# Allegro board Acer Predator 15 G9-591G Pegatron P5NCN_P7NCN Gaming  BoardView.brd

Outline 272.5 x 186.7 mm; copper layers: TOP, GND1, IN1, GND2, IN2, IN3, GND3, IN4, GND4, BOTTOM. Coordinates in mm from the lower left corner of the outline.

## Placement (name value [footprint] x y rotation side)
C300  -  [VX_C0402_H28_SMALL]  174.54 151.4 180 top
C301  -  [VX_C0402_SMALL]  176.07 151.37 270 top
C302  -  [VX_C0402_SMALL]  168.45 148.61 90 top
C401  -  [VX_C0402_SMALL]  205.76 150.28 90 top
C402  -  [VX_C0402_SMALL]  206.66 147.16 180 top
C0500  -  [VX_C0402_SMALL]  16.05 126.79 270 top
C0501  -  [VX_C0402_SMALL]  14.78 123.71 0 top
C0502  -  [VX_C0402_SMALL]  14.97 130.08 0 top
C0503  -  [VX_C0402_SMALL]  10.62 126.79 270 top
C0504  -  [VX_C0402_SMALL]  12.34 126.79 90 top
C0505  -  [VX_C0402_SMALL]  13.18 126.79 90 top
C0600  -  [VX_C0402_SMALL]  75.11 149.7 0 top
C0601  -  [VX_C0402_SMALL]  77.78 148.3 0 top
C0602  -  [VX_C0402_SMALL]  77.78 147.41 0 top
C0603  -  [VX_C0402_SMALL]  75.24 146.02 0 top
C0604  -  [VX_C0402_SMALL]  78.28 145.51 0 top
C0605  -  [VX_C0402_SMALL]  75.24 144.11 0 top
C0606  -  [VX_C0402_SMALL]  78.28 142.71 0 top
C0607  -  [VX_C0402_SMALL]  75.11 148.81 0 top
C0608  -  [VX_C0402_SMALL]  75.24 146.91 0 top
C0609  -  [VX_C0402_SMALL]  78.28 144.62 0 top
C0610  -  [VX_C0402_SMALL]  75.24 143.22 0 top
C0611  -  [VX_C0402_SMALL]  78.28 141.83 0 top
C0612  -  [VX_C0402_SMALL]  75.24 140.3 0 top
C0613  -  [VX_C0402_SMALL]  75.24 141.19 0 top
C0614  -  [VX_C0402_SMALL]  78.28 139.03 0 top
C0615  -  [VX_C0402_SMALL]  78.28 139.92 0 top
C0616  -  [VX_C0402_SMALL]  75.24 138.4 0 top
C0617  -  [VX_C0402_SMALL]  75.24 137.51 0 top
C0618  -  [VX_C0402_SMALL]  78.28 136.24 0 top
C0619  -  [VX_C0402_SMALL]  78.28 137.13 0 top
C0620  -  [VX_C0402_SMALL]  75.24 135.73 0 top
C0621  -  [VX_C0402_SMALL]  75.24 134.84 0 top
C0622  -  [VX_C0402_SMALL]  78.28 133.52 0 top
C0623  -  [VX_C0402_SMALL]  78.28 134.41 0 top
C0624  -  [VX_C0402_SMALL]  75.24 132.94 0 top
C0625  -  [VX_C0402_SMALL]  75.24 132.05 0 top
C0626  -  [VX_C0402_SMALL]  78.28 130.65 0 top
C0627  -  [VX_C0402_SMALL]  78.28 131.54 0 top
C0628  -  [VX_C0402_SMALL]  75.24 130.14 0 top
C0629  -  [VX_C0402_SMALL]  75.24 129.25 0 top
C0630  -  [VX_C0402_SMALL]  78.28 127.86 0 top
C0631  -  [VX_C0402_SMALL]  78.28 128.74 0 top
C0701  -  [VX_C0402_SMALL]  16.76 127.12 270 bottom
C0702  -  [VX_C0402_SMALL]  113.93 50.85 90 top
C0703  -  [VX_C0402_SMALL]  113.08 50.85 270 top
C0900  -  [VX_C0201_H14]  47.42 149.37 180 top
C0901  -  [VX_C0201_H14]  44.88 134 180 top
C0902  -  [VX_C0201_H14]  50.09 143.73 180 top
C0903  -  [VX_C0201_H14]  50.09 145.25 180 top
C0904  -  [VX_C0201_H14]  44.63 145.89 180 top
C0905  -  [VX_C0201_H14]  47.42 143.73 0 top
C0906  -  [VX_C0201_H14]  47.42 145.25 0 top
C0907  -  [VX_C0201_H14]  53.52 137.79 0 top
C0908  -  [VX_C0201_H14]  52.12 147.59 180 top
C0909  -  [VX_C0201_H14]  51.99 134 180 top
C0910  -  [VX_C0201_H14]  44.88 134.76 180 top
C0911  -  [VX_C0201_H14]  55.17 135.85 180 top
C0912  -  [VX_C0201_H14]  44.88 137.79 180 top
C0913  -  [VX_C0201_H14]  55.17 135.09 180 top
C0914  -  [VX_C0201_H14]  48.57 135.52 180 top
C0915  -  [VX_C0201_H14]  53.39 144.49 0 top
C0916  -  [VX_C0201_H14]  47.42 144.49 0 top
C0917  -  [VX_C0201_H14]  50.09 146.02 180 top
C0918  -  [VX_C0201_H14]  47.42 146.02 0 top
C0919  -  [VX_C0201_H14]  47.04 134 0 top
C0920  -  [VX_C0201_H14]  49.73 149.37 180 top
C0921  -  [VX_C0201_H14]  44.88 135.52 180 top
C0922  -  [VX_C0201_H14]  48.57 137.05 180 top
C0923  -  [VX_C0201_H14]  48.57 136.29 180 top
C0924  -  [VX_C0201_H14]  48.57 134.76 180 top
C0925  -  [VX_C0201_H14]  50.47 135.52 0 top
C0926  -  [VX_C0201_H14]  50.47 134.76 0 top
C0927  -  [VX_C0201_H14]  51.99 137.05 180 top
C0928  -  [VX_C0201_H14]  47.04 136.29 0 top
C0929  -  [VX_C0201_H14]  45.01 147.46 180 top
C0930  -  [VX_C0201_H14]  42.6 146.14 270 top
C0931  -  [VX_C0201_H14]  44.63 143.6 180 top
C0932  -  [VX_C0201_H14]  44.63 144.37 180 top
C0933  -  [VX_C0201_H14]  53.52 134.76 0 top
C0934  -  [VX_C0201_H14]  53.52 135.52 0 top
C0935  -  [VX_C0201_H14]  53.52 134 0 top
C0936  -  [VX_C0201_H14]  53.52 136.29 0 top
C0937  -  [VX_C0201_H14]  47.04 137.05 0 top
C0938  -  [VX_C0201_H14]  45.01 149.37 180 top
C0939  -  [VX_C0201_H14]  43.36 146.14 270 top
C0940  -  [VX_C0201_H14]  53.39 145.25 0 top
C0941  -  [VX_C0201_H14]  53.39 146.02 0 top
C0942  -  [VX_C0201_H14]  51.99 134.76 180 top
C0943  -  [VX_C0201_H14]  51.99 135.52 180 top
C0944  -  [VX_C0201_H14]  51.99 136.29 180 top
C0945  -  [VX_C0201_H14]  50.09 144.49 180 top
C0946  -  [VX_C0201_H14]  47.42 147.59 180 top
C0947  -  [VX_C0201_H14]  50.47 134 0 top
C0948  -  [VX_C0201_H14]  47.04 135.52 0 top
C0949  -  [VX_C0201_H14]  47.04 134.76 0 top
C0950  -  [VX_C0201_H14]  44.88 136.29 180 top
C0951  -  [VX_C0201_H14]  44.88 137.05 180 top
C0952  -  [VX_C0201_H14]  50.47 137.05 0 top
C0953  -  [VX_C0201_H14]  50.47 136.29 0 top
C0954  -  [VX_C0201_H14]  53.52 137.05 0 top
C0955  -  [VX_C0201_H14]  49.73 147.59 180 top
C0956  -  [VX_C0201_H14]  52.12 149.37 180 top
C0957  -  [VX_C0201_H14]  44.63 145.13 180 top
C0958  -  [VX_C0201_H14]  47.04 137.79 0 top
C0959  -  [VX_C0201_H14]  53.39 143.73 0 top
C0960  -  [VX_C0201_H14]  55.17 134.33 180 top
C0961  -  [VX_C0201_H14]  55.17 136.62 180 top
C0962  -  [VX_C0201_H14]  48.57 134 180 top
C0963  -  [VX_C0201_H14]  36.25 136.13 180 top
C0964  -  [VX_C0201_H14]  38.28 134.56 0 top
C0965  -  [VX_C0201_H14]  40.82 134.63 0 top
C0966  -  [VX_C0201_H14]  39.04 144.41 180 top
C0967  -  [VX_C0201_H14]  33.45 136.11 0 top
C0968  -  [VX_C0201_H14]  30.02 145.94 180 top
C0969  -  [VX_C0201_H14]  34.34 143.65 180 top
C0970  -  [VX_C0201_H14]  32.82 145.94 0 top
C0971  -  [VX_C0201_H14]  30.66 134.51 180 top
C0972  -  [VX_C0201_H14]  40.82 136.92 0 top
C0973  -  [VX_C0201_H14]  32.82 142.13 0 top
C0974  -  [VX_C0201_H14]  37.52 145.94 0 top
C0975  -  [VX_C0201_H14]  32.82 145.18 0 top
C0976  -  [VX_C0201_H14]  34.34 145.94 180 top
C0977  -  [VX_C0201_H14]  40.31 147.46 0 top
C0978  -  [VX_C0201_H14]  39.04 142.13 180 top
C0979  -  [VX_C0201_H14]  28.5 142.89 0 top
C0980  -  [VX_C0201_H14]  34.34 142.13 180 top
C0981  -  [VX_C0201_H14]  30.66 136.03 180 top
C0982  -  [VX_C0201_H14]  30.66 136.79 180 top
C0983  -  [VX_C0201_H14]  30.02 142.13 180 top
C0984  -  [VX_C0201_H14]  39.04 142.89 180 top
C0985  -  [VX_C0201_H14]  37.52 142.13 0 top
C0986  -  [VX_C0201_H14]  28.5 147.46 180 top
C0987  -  [VX_C0201_H14]  30.91 147.46 0 top
C0988  -  [VX_C0201_H14]  30.02 144.41 180 top
C0989  -  [VX_C0201_H14]  30.02 143.65 180 top
C0990  -  [VX_C0201_H14]  30.02 145.18 180 top
C0991  -  [VX_C0201_H14]  34.34 144.41 180 top
C0992  -  [VX_C0201_H14]  36.25 136.87 180 top
C0993  -  [VX_C0201_H14]  38.28 135.32 0 top
C0994  -  [VX_C0201_H14]  40.82 135.4 0 top
C0995  -  [VX_C0201_H14]  39.04 145.18 180 top
C0996  -  [VX_C0201_H14]  39.04 145.94 180 top
C0997  -  [VX_C0201_H14]  28.5 145.94 0 top
C0998  -  [VX_C0201_H14]  35.61 149.37 0 top
C0999  -  [VX_C0201_H14]  30.91 149.37 0 top
C1000  -  [VX_C0603_H39_SMALL]  68.91 126.46 0 bottom
C1001  -  [VX_C0402_SMALL]  26.21 133.21 270 top
C1002  -  [VX_C0402_SMALL]  28.09 132.63 180 top
C1003  -  [VX_C0402_H26_SMALL]  57.58 146.06 0 top
C1004  -  [VX_C0402_SMALL]  55.27 144.21 0 top
C1005  -  [VX_C0402_SMALL]  55.27 143.32 0 top
C1006  -  [VX_C0402_H26_SMALL]  57.58 145.18 0 top
C1007  -  [VX_C0603_SMALL]  33.88 130.65 180 top
C1008  -  [VX_C0603_SMALL]  52.27 125.24 270 top
C1009  -  [VX_C0603_SMALL]  42.6 133.82 90 top
C1010  -  [VX_C0603_SMALL]  47.42 125.24 270 top
C1011  -  [VX_C0603_SMALL]  51.82 129.34 90 top
C1012  -  [VX_C0603_SMALL]  46.28 129.3 90 top
C1013  -  [VX_C0603_SMALL]  54.53 129.05 90 top
C1014  -  [VX_C0603_SMALL]  33.45 129.13 180 top
C1015  -  [VX_C0603_SMALL]  35.23 128.67 90 top
C1016  -  [VX_C0603_SMALL]  57.58 126.46 0 top
C1101  -  [VX_C0201]  238.18 25.87 90 top
C1102  -  [VX_C0201]  238.94 25.87 90 top
C1103  -  [VX_C0201]  241.86 25.87 90 top
C1104  -  [VX_C0201]  241.1 25.87 90 top
C1105  -  [VX_C0201]  244.29 25.75 90 top
C1106  -  [VX_C0201]  243.53 25.75 90 top
C1107  -  [VX_C0201]  246.69 25.75 90 top
C1108  -  [VX_C0201]  245.92 25.75 90 top
C1119  -  [VX_C0201]  230.77 38.37 0 top
C1120  -  [VX_C0201]  230.77 37.66 0 top
C1121  -  [VX_C0201]  232.9 36.42 0 top
C1122  -  [VX_C0201]  232.9 35.71 0 top
C1123  -  [VX_C0201]  230.5 35.2 0 top
C1124  -  [VX_C0201]  230.5 34.49 0 top
C1125  -  [VX_C0201]  232.9 34.12 0 top
C1126  -  [VX_C0201]  232.9 33.41 0 top
C1129  -  [VX_C0402_SMALL]  222.68 52.6 270 top
C1130  -  [VX_C0402_SMALL]  251.26 25.75 180 top
C1131  -  [VX_C0402_SMALL]  248.72 25.75 0 top
C1132  -  [VX_C0201]  251.51 32.04 0 top
C1133  -  [VX_C0201]  251.51 31.33 0 top
C1134  -  [VX_C0201]  251.51 29.8 0 top
C1135  -  [VX_C0201]  251.51 30.51 0 top
C1136  -  [VX_C0201]  234.85 31.52 0 bottom
C1137  -  [VX_C0201]  234.85 32.23 0 bottom
C1138  -  [VX_C0201]  231.02 32.68 0 top
C1139  -  [VX_C0201]  231.02 31.97 0 top
C1140  -  [VX_C0201]  232.73 31.21 0 top
C1141  -  [VX_C0201]  232.73 30.5 0 top
C1142  -  [VX_C0201]  228.73 30.12 0 top
C1143  -  [VX_C0201]  228.73 30.83 0 top
C1144  -  [VX_C0201]  233.94 28.03 0 top
C1145  -  [VX_C0201]  233.94 27.32 0 top
C1146  -  [VX_C0201]  234.87 33.04 0 bottom
C1147  -  [VX_C0201]  234.87 33.75 0 bottom
C1148  -  [VX_C0402_SMALL]  246.62 32.44 90 bottom
C1149  -  [VX_C0402_SMALL]  246.61 34.04 270 bottom
C1150  -  [VX_C0402_SMALL]  247.47 34.04 270 bottom
C1151  -  [VX_C0402_SMALL]  249.51 32.15 90 bottom
C1152  -  [VX_C0402_SMALL]  248.67 32.15 90 bottom
C1153  -  [VX_C0402_SMALL]  249.1 34.89 0 bottom
C1154  -  [VX_C0402_SMALL]  247.46 32.44 90 bottom
C1155  -  [VX_C0603_SMALL]  250.5 38.7 90 top
C1156  -  [VX_C0603_SMALL]  251.77 38.7 90 top
C1157  -  [VX_C0603_SMALL]  253.04 38.7 90 top
C1158  -  [VX_C0603_SMALL]  249.23 38.7 90 top
C1159  -  [VX_C0805_H57_SMALL]  253.16 41.88 90 top
C1160  -  [VX_C0805_H57_SMALL]  254.94 41.88 90 top
C1161  -  [VX_C0805_H57_SMALL]  251.38 41.88 90 top
C1163  -  [VX_C0603_SMALL]  248.15 29.44 0 bottom
C1164  -  [VX_C0603_SMALL]  248.16 30.67 0 bottom
C1165  -  [VX_C0201_H14]  244.16 32.73 180 bottom
C1166  -  [VX_C0201_H14]  244.16 33.47 180 bottom
C1167  -  [VX_C0201_H14]  241.86 35.91 180 bottom
C1168  -  [VX_C0201_H14]  243.13 34.64 180 bottom
C1169  -  [VX_C0201_H14]  243.59 36.11 0 bottom
C1170  -  [VX_C0201_H14]  243.16 38.6 90 bottom
C1171  -  [VX_C0201_H14]  239.8 34.76 180 bottom
C1172  -  [VX_C0201_H14]  242.44 38.6 90 bottom
C1173  -  [VX_C0201_H14]  243.13 35.37 180 bottom
C1174  -  [VX_C0201_H14]  242.86 30.36 270 bottom
C1175  -  [VX_C0201_H14]  242.86 33.64 90 bottom
C1176  -  [VX_C0201_H14]  242.74 32.66 0 bottom
C1177  -  [VX_C0201_H14]  242.75 29.02 0 bottom
C1178  -  [VX_C0201_H14]  240.79 33.32 270 bottom
C1179  -  [VX_C0201_H14]  241.12 34.64 0 bottom
C1180  -  [VX_C0201_H14]  240.86 35.63 90 bottom
C1181  -  [VX_C0201_H14]  240.92 32.1 90 bottom
C1182  -  [VX_C0201_H14]  240.92 30.85 270 bottom
C1183  -  [VX_C0201_H14]  242.86 31.66 270 bottom
C1184  -  [VX_C0201_H14]  243.59 31.04 270 bottom
C1185  -  [VX_C0201_H14]  240.59 38.19 90 bottom
C1186  -  [VX_C0201_H14]  247.1 35.47 270 bottom
C1187  -  [VX_C0201_H14]  242.12 33.8 90 bottom
C1188  -  [VX_C0201_H14]  244.53 34.64 180 bottom
C1189  -  [VX_C0201]  234.87 34.71 0 bottom
C1190  -  [VX_C0201]  234.87 35.47 0 bottom
C1191  -  [VX_C0805_H57_SMALL]  228.87 37.04 270 bottom
C1192  -  [VX_C0805_H57_SMALL]  230.65 37.04 270 bottom
C1193  -  [VX_C0201]  240.59 41.11 180 top
C1194  -  [VX_C0201]  241.86 40.1 180 top
C1195  -  [VX_C0201]  242.88 41.11 180 top
C1196  -  [VX_C0201]  243.89 40.1 180 top
C1203  -  [VX_C0603_SMALL]  243.64 45.99 270 top
C1204  -  [VX_C0402_SMALL]  237.16 47.59 0 top
C1205  -  [VX_C0402_SMALL]  244.88 46.07 90 top
C1206  -  [VX_C0603_SMALL]  242.11 45.99 270 top
C1207  -  [VX_C0603_SMALL]  246.91 45.34 0 top
C1208  -  [VX_C0603_SMALL]  234.61 47.46 0 top
C1209  -  [VX_C0603_H39_SMALL]  235.38 53.31 270 top
C1210  -  [VX_C0603_H39_SMALL]  232.84 53.18 270 top
C1211  -  [VX_C0603_H39_SMALL]  234.11 53.31 270 top
C1212  -  [VX_C0402_SMALL]  236.53 53.31 90 top
C1217  -  [VX_C0603_SMALL]  247.5 54.96 270 top
C1218  -  [VX_C0402_SMALL]  246 55.12 270 top
C1219  -  [VX_C0402_SMALL]  244.78 55.59 270 top
C1220  -  [VX_C0201]  257.48 19.91 270 bottom
C1221  -  [VX_C0603_SMALL]  234.61 45.81 0 top
C1222  -  [VX_C0805_H57_SMALL]  256.21 20.67 90 bottom
C1223  -  [VX_C0402_SMALL]  251.13 49.37 180 top
C1224  -  [VX_C0402_SMALL]  251.13 51.1 180 top
C1225  -  [VX_C0201]  265.74 25.37 180 bottom
C1226  -  [VX_C0201]  265.74 27.4 180 bottom
C1227  -  [VX_C0201]  265.74 24.6 180 bottom
C1228  -  [VX_C0201]  265.74 26.64 180 bottom
C1229  -  [VX_C0402_SMALL]  232.56 48.79 0 bottom
C1301  -  [VX_C0402_SMALL]  217.6 50.51 90 top
C1302  -  [VX_C0402_SMALL]  208.51 59.04 0 top
C1303  -  [VX_C0603_SMALL]  210.46 59.2 180 top
C1304  -  [VX_C0603_SMALL]  206.77 48.3 180 top
C1305  -  [VX_C0402_SMALL]  206.81 57.16 180 top
C1306  -  [VX_C0402_SMALL]  206.55 51.45 180 top
C1307  -  [VX_C0402_SMALL]  206.55 53.61 180 top
C1308  -  [VX_C0402_SMALL]  206.54 50.49 180 top
C1309  -  [VX_C0402_SMALL]  206.81 58.05 180 top
C1310  -  [VX_C0402_SMALL]  206.53 49.6 180 top
C1313  -  [VX_C0402_SMALL]  206.55 52.34 180 top
C1314  -  [VX_C0402_SMALL]  206.55 54.5 180 top
C1315  -  [VX_C0402_SMALL]  210.82 62.37 180 top
C1316  -  [VX_C0402_SMALL]  210.82 63.26 180 top
C1401  -  [VX_C0402_SMALL]  205.79 42.81 180 top
C1402  -  [VX_C0402_SMALL]  205.79 39.13 180 top
C1403  -  [VX_C0402_SMALL]  205.79 37.1 180 top
C1404  -  [VX_C0402_SMALL]  205.79 36.08 180 top
C1405  -  [VX_C0402_SMALL]  205.79 43.7 180 top
C1406  -  [VX_C0402_SMALL]  205.79 35.07 180 top
C1407  -  [VX_C0402_SMALL]  203.94 46.24 180 top
C1408  -  [VX_C0402_SMALL]  203.94 47.13 180 top
C1409  -  [VX_C0402_SMALL]  205.79 38.11 180 top
C1410  -  [VX_C0402_SMALL]  205.79 40.15 180 top
C1411  -  [VX_C0603_SMALL]  208.84 33.92 270 top
C1412  -  [VX_C0603_SMALL]  207.33 44.82 90 top
C1413  -  [VX_C0402_SMALL]  212.27 34.18 90 top
C1414  -  [VX_C0402_SMALL]  207.57 34.05 270 top
C1600  -  [VX_C0402_SMALL]  95.56 82.06 0 bottom
C1601  -  [VX_C0402_SMALL]  95.56 81.17 0 bottom
C1602  -  [VX_C0402_SMALL]  57.2 83.96 180 bottom
C1603  -  [VX_C0402_SMALL]  57.2 81.29 180 bottom
C1604  -  [VX_C0402_H24_SMALL]  89.84 82.92 0 bottom
C1605  -  [VX_C0402_SMALL]  89.84 82.06 180 bottom
C1606  -  [VX_C0402_SMALL]  89.84 81.17 0 bottom
C1607  -  [VX_C0402_H24_SMALL]  82.98 54.73 180 bottom
C1608  -  [VX_C0402_SMALL]  90.48 54.73 180 bottom
C1609  -  [VX_C0402_SMALL]  88.39 54.73 180 bottom
C1610  -  [VX_C0402_SMALL]  76.38 86.12 0 bottom
C1612  -  [VX_C0402_H28_SMALL]  76.38 82.56 180 bottom
C1613  -  [VX_C0402_SMALL]  76.38 81.29 180 bottom
C1614  -  [VX_C0402_H28_SMALL]  78.71 82.62 0 bottom
C1615  -  [VX_C0402_SMALL]  78.28 81.29 0 bottom
C1616  -  [VX_C0402_SMALL]  80.47 67.2 180 top
C1617  -  [VX_C0402_SMALL]  90.17 67.2 0 top
C1618  -  [VX_C0402_SMALL]  76.38 87.01 180 bottom
C1619  -  [VX_C0402_SMALL]  66.22 81.17 0 bottom
C1620  -  [VX_C0402_SMALL]  67.67 83.83 180 bottom
C1700  -  [VX_C0402_SMALL]  95.81 54.77 0 bottom
C1701  -  [VX_C0402_SMALL]  99.37 67.2 0 top
C1702  -  [VX_C0402_SMALL]  57.2 83.07 180 bottom
C1703  -  [VX_C0402_SMALL]  57.2 82.18 180 bottom
C1704  -  [VX_C0402_H24_SMALL]  93.9 82.95 0 bottom
C1705  -  [VX_C0402_SMALL]  93.9 81.04 180 bottom
C1706  -  [VX_C0402_SMALL]  93.9 82.06 0 bottom
C1707  -  [VX_C0402_SMALL]  107.73 52.01 0 top
C1708  -  [VX_C0402_H24_SMALL]  107.73 52.87 180 top
C1709  -  [VX_C0402_SMALL]  97.71 67.2 0 top
C1710  -  [VX_C0402_SMALL]  35.23 89.8 0 bottom
C1712  -  [VX_C0402_SMALL]  34.98 86.12 0 bottom
C1713  -  [VX_C0402_H28_SMALL]  75.11 54.75 180 bottom
C1714  -  [VX_C0402_SMALL]  37.26 86.12 180 bottom
C1717  -  [VX_C0402_SMALL]  35.23 90.69 180 bottom
C1718  -  [VX_C0402_SMALL]  71.86 54.75 180 bottom
C1719  -  [VX_C0402_SMALL]  107.47 61.46 0 bottom
C1800  -  [VX_C0402_H24_SMALL]  61.01 82.44 180 bottom
C1801  -  [VX_C0402_H24_SMALL]  50.72 81.17 180 bottom
C1802  -  [VX_C0402_H24_SMALL]  70.51 81.32 180 bottom
C1803  -  [VX_C0402_H24_SMALL]  70.51 82.59 180 bottom
C1804  -  [VX_C0402_H24_SMALL]  50.72 82.06 180 bottom
C1805  -  [VX_C0402_H24_SMALL]  63.68 82.44 0 bottom
C1806  -  [VX_C0402_H24_SMALL]  61.01 81.17 180 bottom
C1807  -  [VX_C0402_H24_SMALL]  63.68 81.17 0 bottom
C1808  -  [VX_C0402_H24_SMALL]  95.59 84.72 0 bottom
C1809  -  [VX_C0402_H24_SMALL]  95.56 82.95 0 bottom
C1810  -  [VX_C0402_H24_SMALL]  72.7 82.59 0 bottom
C1811  -  [VX_C0402_H24_SMALL]  68.53 82.54 0 bottom
C1812  -  [VX_C0402_H24_SMALL]  72.7 81.32 0 bottom
C1813  -  [VX_C0402_H24_SMALL]  43.1 81.68 0 bottom
C1814  -  [VX_C0402_H24_SMALL]  68.53 81.27 0 bottom
C1815  -  [VX_C0402_H24_SMALL]  43.1 82.56 0 bottom
C1816  -  [VX_C0402_H24_SMALL]  85.36 82.95 0 bottom
C1817  -  [VX_C0402_H24_SMALL]  85.36 81.68 0 bottom
C1818  -  [VX_C0402_H24_SMALL]  95.56 83.83 0 bottom
C1819  -  [VX_C0402_H24_SMALL]  97.42 54.77 180 bottom
C1820  -  [VX_C0402_H24_SMALL]  101.02 67.2 180 top
C1821  -  [VX_C0402_H24_SMALL]  95.59 85.61 0 bottom
C1822  -  [VX_C0402_SMALL]  80.19 54.75 180 bottom
C1823  -  [VX_C0402_SMALL]  65.79 67.2 180 top
C1824  -  [VX_C0402_SMALL]  68.07 67.2 180 top
C1825  -  [VX_C0402_SMALL]  71.94 67.2 0 top
C1826  -  [VX_C0402_SMALL]  85.27 54.7 0 bottom
C1827  -  [VX_C0402_SMALL]  40.69 81.68 180 bottom
C1828  -  [VX_C0402_SMALL]  76.51 67.2 180 top
C1829  -  [VX_C0402_SMALL]  40.69 82.56 180 bottom
C1832  -  [VX_C0402_SMALL]  46.8 67.2 0 top
C1833  -  [VX_C0402_SMALL]  41.12 67.2 0 top
C1834  -  [VX_C0402_SMALL]  96.06 67.2 180 top
C1835  -  [VX_C0402_SMALL]  84.69 67.2 0 top
C1836  -  [VX_C0402_SMALL]  51.69 67.2 0 top
C1837  -  [VX_C0402_SMALL]  35.99 67.2 0 top
C1838  -  [VX_C0402_SMALL]  61.44 67.2 180 top
C1839  -  [VX_C0402_SMALL]  57.83 67.2 180 top
C1840  -  [VX_C0402_SMALL]  106.13 68.1 270 top
C1841  -  [VX_C0402_SMALL]  105.24 68.1 270 top
C1842  -  [VX_C0402_SMALL]  108.94 59.07 180 top
C1843  -  [VX_C0402_H24_SMALL]  43.79 67.18 180 top
C1844  -  [VX_C0402_H24_SMALL]  108.13 68.67 180 bottom
C1845  -  [VX_C0402_H24_SMALL]  42.27 107.66 270 top
C1846  -  [VX_C0402_SMALL]  41.38 107.66 270 top
C1847  -  [VX_C0402_SMALL]  108.13 67.78 180 bottom
C1848  -  [VX_C0402_SMALL]  38.79 85.18 0 bottom
C2000  -  [VX_C0402_SMALL]  152.45 47.26 180 bottom
C2001  -  [VX_C0402_SMALL]  152.45 48.15 180 bottom
C2002  -  [VX_C0402_SMALL]  150.52 53.18 0 bottom
C2003  -  [VX_C0402_SMALL]  150.52 54.07 0 bottom
C2004  -  [VX_C0402_SMALL]  150.04 58.18 0 bottom
C2005  -  [VX_C0402_SMALL]  150.04 59.07 0 bottom
C2006  -  [VX_C0402_SMALL]  152.45 57.16 0 bottom
C2007  -  [VX_C0402_SMALL]  152.45 56.28 0 bottom
C2009  -  [VX_C0402_SMALL]  150.52 55.85 0 bottom
C2011  -  [VX_C0402_SMALL]  150.52 54.96 0 bottom
C2012  -  [VX_C0402_SMALL]  150.04 48.53 180 bottom
C2013  -  [VX_C0402_SMALL]  150.04 49.42 180 bottom
C2014  -  [VX_C0402_SMALL]  150.04 46.88 180 bottom
C2015  -  [VX_C0402_SMALL]  150.04 45.99 180 bottom
C2016  -  [VX_C0402_SMALL]  152.45 44.72 180 bottom
C2017  -  [VX_C0402_SMALL]  152.45 45.61 180 bottom
C2018  -  [VX_C0402_SMALL]  150.04 43.58 180 bottom
C2019  -  [VX_C0402_SMALL]  150.04 44.46 180 bottom
C2020  -  [VX_C0402_SMALL]  152.45 50.69 180 bottom
C2021  -  [VX_C0402_SMALL]  152.45 49.8 180 bottom
C2200  -  [VX_C0402_SMALL]  185.6 60.09 0 top
C2201  -  [VX_C0402_SMALL]  172.29 67.58 90 bottom
C2202  -  [VX_C0402_SMALL]  188.27 56.53 180 top
C2203  -  [VX_C0402_SMALL]  190.93 56.78 180 bottom
C2204  -  [VX_C0402_SMALL]  188.27 46.24 180 bottom
C2300  -  [VX_C0402_SMALL]  186.74 70.25 270 bottom
C2301  -  [VX_C0402_SMALL]  185.85 70.25 270 bottom
C2302  -  [VX_C0402_SMALL]  187.63 70.25 270 bottom
C2303  -  [VX_C0402_SMALL]  184.07 70.25 270 bottom
C2304  -  [VX_C0402_SMALL]  181.41 36.34 270 top
C2305  -  [VX_C0402_SMALL]  182.37 36.34 90 top
C2306  -  [VX_C0402_SMALL]  183.57 33.67 90 bottom
C2307  -  [VX_C0402_SMALL]  180.52 36.34 270 top
C2308  -  [VX_C0402_SMALL]  178.32 36.34 270 top
C2309  -  [VX_C0402_SMALL]  182.55 36.34 90 bottom
C2310  -  [VX_C0402_SMALL]  184.96 70.25 270 bottom
C2400  -  [VX_C0402_SMALL]  181.92 64.4 90 top
C2401  -  [VX_C0402_SMALL]  185.6 60.33 0 bottom
C2402  -  [VX_C0402_SMALL]  188.65 62.37 90 top
C2403  -  [VX_C0402_SMALL]  175.36 20.39 90 top
C2404  -  [VX_C0402_SMALL]  192.33 69.86 0 bottom
C2405  -  [VX_C0402_SMALL]  196.65 67.91 0 bottom
C2500  -  [VX_C0402_SMALL]  186.13 63.64 270 bottom
C2501  -  [VX_C0402_SMALL]  186.13 62.02 90 bottom
C2502  -  [VX_C0402_SMALL]  154.23 63.72 180 bottom
C2503  -  [VX_C0402_SMALL]  152.58 63.72 0 bottom
C2600  -  [VX_C0603_H39_SMALL]  173.28 51.2 0 top
C2601  -  [VX_C0603_H39_SMALL]  173.28 49.93 0 top
C2602  -  [VX_C0402_SMALL]  174.31 41.64 90 top
C2603  -  [VX_C0402_SMALL]  181.03 41.92 90 top
C2604  -  [VX_C0402_SMALL]  170.33 41.54 90 top
C2605  -  [VX_C0603_H39_SMALL]  162.36 65.55 180 top
C2606  -  [VX_C0603_H39_SMALL]  162.36 64.28 180 top
C2607  -  [VX_C0402_SMALL]  162.48 63.13 0 top
C2608  -  [VX_C0603_H39_SMALL]  161.7 46.83 270 top
C2609  -  [VX_C0402_SMALL]  168.07 48.61 180 top
C2610  -  [VX_C0402_SMALL]  182.8 62.4 270 top
C2611  -  [VX_C0603_H39_SMALL]  188.52 68.59 90 top
C2612  -  [VX_C0603_H39_SMALL]  187.25 68.59 90 top
C2613  -  [VX_C0603_H39_SMALL]  152.32 38.62 180 bottom
C2614  -  [VX_C0805_H57_SMALL]  152.32 40.4 0 bottom
C2615  -  [VX_C0402_SMALL]  155.38 42.25 270 bottom
C2616  -  [VX_C0402_SMALL]  182.32 55.44 270 top
C2617  -  [VX_C0402_SMALL]  183.19 55.44 270 top
C2618  -  [VX_C0603_H39_SMALL]  174.66 53.26 270 top
C2619  -  [VX_C0603_H39_SMALL]  173.79 62.75 90 top
C2620  -  [VX_C0402_SMALL]  173.48 69.99 270 top
C2621  -  [VX_C0402_SMALL]  171.76 70.45 0 top
C2622  -  [VX_C0402_SMALL]  183.13 46.93 270 top
C2623  -  [VX_C0402_SMALL]  190.93 50.94 180 top
C2624  -  [VX_C0402_SMALL]  181.28 51.96 90 top
C2625  -  [VX_C0402_SMALL]  182.68 51.96 90 top
C2629  -  [VX_C0402_SMALL]  181.33 58.56 270 top
C2630  -  [VX_C0402_SMALL]  193.35 45.18 0 top
C2826  -  [VX_C0402_SMALL]  222.05 58.01 90 bottom
C2827  -  [VX_C0402_SMALL]  221.16 56.36 90 bottom
C2828  -  [VX_C0402_SMALL]  219.18 56.36 90 bottom
C3000  -  [VX_C0805_H57_SMALL]  110.54 48.48 270 top
C3001  -  [VX_C0402_SMALL]  130.1 38.07 0 top
C3002  -  [VX_C0402_SMALL]  130.1 41.04 180 top
C3003  -  [VX_C0402_SMALL]  108.79 36.34 0 top
C3004  -  [VX_C0402_SMALL]  122.99 26.94 90 top
C3009  -  [VX_C0402_SMALL]  123.01 47.87 270 top
C3011  -  [VX_C0402_SMALL]  119.96 47.61 270 top
C3015  -  [VX_C0402_SMALL]  122 48.05 90 top
C3019  -  [VX_C0805_H57_SMALL]  112.45 48.48 270 top
C3020  -  [VX_C0402_SMALL]  113.75 48.01 270 top
C3021  -  [VX_C0402_SMALL]  115.9 27.07 180 top
C3022  -  [VX_C0402_SMALL]  120.98 48.05 270 top
C3023  -  [VX_C0402_SMALL]  126.16 48.27 270 top
C3024  -  [VX_C0402_SMALL]  114.67 48.01 270 top
C3025  -  [VX_C0402_SMALL]  130.1 43.53 180 top
C3100  -  [VX_C0402_SMALL]  196.77 25.19 270 top
C3101  -  [VX_C0402_SMALL]  200.79 32.22 270 top
C3102  -  [VX_C0402_SMALL]  178.32 32.02 0 bottom
C3103  -  [VX_C0402_SMALL]  180.54 32.02 180 bottom
C3104  -  [VX_C0603_SMALL]  223.32 44.8 90 bottom
C3105  -  [VX_C0402_SMALL]  225.1 51.27 180 bottom
C3300  -  [VX_C0402_SMALL]  228.27 86.71 0 top
C3301  -  [VX_C0402_SMALL]  228.27 85.82 0 top
C3302  -  [VX_C0603_SMALL]  228.27 84.75 180 top
C3303  -  [VX_C0402_SMALL]  227.25 88.91 90 bottom
C3304  -  [VX_C0402_SMALL]  226.37 88.91 90 bottom
C3305  -  [VX_C0603_SMALL]  225.27 88.91 270 bottom
C3306  -  [VX_C0402_SMALL]  228.24 87.57 180 top
C3307  -  [VX_C0402_SMALL]  228.24 88.41 180 top
C3308  -  [VX_C0402_SMALL]  223.6 90.29 180 top
C3309  -  [VX_C0603_SMALL]  224.59 95.77 90 bottom
C3310  -  [VX_C0603_SMALL]  231.32 92.39 90 bottom
C3311  -  [VX_C0603_SMALL]  223.32 93.61 180 bottom
C3312  -  [VX_C0603_SMALL]  231.32 89.55 270 bottom
C3313  -  [VX_C0402_SMALL]  222.43 91.58 0 top
C3314  -  [VX_C0402_SMALL]  222.43 92.47 0 top
C3315  -  [VX_C0402_SMALL]  233.83 93.35 180 top
C3316  -  [VX_C0402_SMALL]  232.59 93.08 90 top
C3317  -  [VX_C0402_SMALL]  232.59 96.53 270 top
C3318  -  [VX_C0402_SMALL]  231.7 96.53 270 top
C3319  -  [VX_C0402_SMALL]  224.33 95.26 270 top
C3320  -  [VX_C0402_SMALL]  229.07 97.57 270 bottom
C3321  -  [VX_C0402_SMALL]  226.67 97.68 270 bottom
C3322  -  [VX_C0402_SMALL]  225.73 96.03 270 bottom
C3323  -  [VX_C0402_SMALL]  230.18 92.39 270 bottom
C3324  -  [VX_C0402_SMALL]  234.11 94.96 270 top
C3325  -  [VX_C0402_SMALL]  234.11 96.61 270 top
C3400  -  [VX_C0402_SMALL]  239.78 147.89 0 top
C3401  -  [VX_C1206_H75]  256.08 148.56 180 top
C3402  -  [VX_C0402_SMALL]  246.81 146.14 180 bottom
C3403  -  [VX_C0402_SMALL]  254.33 133.95 225 top
C3404  -  [VX_C0402_SMALL]  256.95 131.42 225 top
C3600  -  [VX_C0603_SMALL]  14.15 70.32 180 top
C3601  -  [VX_C0603_SMALL]  13.64 72.8 90 top
C3602  -  [VX_C0603_SMALL]  13.69 66.51 90 top
C3603  -  [VX_C0402_SMALL]  16.43 67.58 90 bottom
C3604  -  [VX_C0402_SMALL]  17.07 68.85 180 bottom
C3605  -  [VX_C0603_SMALL]  14.99 75.25 0 top
C3606  -  [VX_C0402_SMALL]  15.8 73.55 180 top
C3607  -  [VX_C0603_SMALL]  19.61 77.36 90 top
C3608  -  [VX_C0402_SMALL]  14.4 62.27 270 top
C3609  -  [VX_C0603_SMALL]  13.26 62.4 90 top
C3610  -  [VX_C0402_SMALL]  17.2 63.9 0 top
C3611  -  [VX_C0603_SMALL]  17.2 62.85 180 top
C3612  -  [VX_C0603_SMALL]  15.69 65.67 90 bottom
C3613  -  [VX_C0603_SMALL]  17.94 65.89 90 bottom
C3614  -  [VX_C0402_SMALL]  21.39 64.15 180 top
C3615  -  [VX_C0603_SMALL]  21.39 63.01 0 top
C3616  -  [VX_C0805_H57_SMALL]  25.86 70.03 180 top
C3617  -  [VX_C0402_SMALL]  22.27 77.98 270 top
C3618  -  [VX_C0402_SMALL]  22.23 80.83 270 top
C3619  -  [VX_C0402_SMALL]  13.82 86.58 0 bottom
C3620  -  [VX_C0402_SMALL]  15.47 86.58 180 bottom
C3621  -  [VX_C0402_SMALL]  17.2 87.47 0 bottom
C3622  -  [VX_C0402_SMALL]  18.85 87.47 180 bottom
C3623  -  [VX_C0805_H57_SMALL]  25.07 62.32 180 top
C3624  -  [VX_C0402_SMALL]  24.73 63.71 180 top
C3626  -  [VX_C0402_SMALL]  23.17 74.44 270 top
C3627  -  [VX_C0402_SMALL]  26.47 66.18 180 top
C3628  -  [VX_C0402_SMALL]  26.47 64.91 180 top
C3629  -  [VX_C0402_SMALL]  25.25 68.74 0 top
C3630  -  [VX_C0402_SMALL]  24.7 72.6 180 top
C3631  -  [VX_C0805_H57_SMALL]  25.21 74.88 180 top
C3633  -  [VX_C0603_SMALL]  12.4 77.82 180 top
C3639  -  [VX_C0603_SMALL]  16.71 76.27 90 top
C3640  -  [VX_C0603_SMALL]  18.11 76.27 90 top
C3642  -  [VX_C0402_SMALL]  24.7 73.48 180 top
C3645  -  [VX_C0402_SMALL]  19.61 78.83 90 bottom
C3646  -  [VX_C0402_SMALL]  17.45 78.71 90 top
C3647  -  [VX_C0402_SMALL]  9.82 72.91 90 top
C3700  -  [VX_C0402_SMALL]  196.39 31.59 0 top
C3701  -  [VX_C0603_SMALL]  197.03 30.45 180 top
C3702  -  [VX_C0402_SMALL]  18.59 78.88 90 bottom
C3703  -  [VX_C0402_SMALL]  17.58 78.88 90 bottom
C3704  -  [VX_C0402_SMALL]  18.59 74.94 270 bottom
C3705  -  [VX_C0402_SMALL]  192.33 34.76 90 bottom
C3706  -  [VX_C0402_SMALL]  192.33 36.42 270 bottom
C3707  -  [VX_C0402_SMALL]  194.62 32.61 270 bottom
C3708  -  [VX_C0402_SMALL]  194.69 30.95 90 bottom
C3709  -  [VX_C0603_SMALL]  202.49 34.82 90 bottom
C3710  -  [VX_C0402_SMALL]  17.58 74.94 270 bottom
C3711  -  [VX_C0402_SMALL]  199.95 29.18 90 top
C4303  -  [VX_C0402_SMALL]  97.58 183.48 90 bottom
C4304  -  [VX_C0402_SMALL]  98.47 183.48 90 bottom
C4305  -  [VX_C0402_SMALL]  92.83 177.06 0 bottom
C4308  -  [VX_C0402_SMALL]  94.79 177.51 90 bottom
C4309  -  [VX_C0402_SMALL]  101.4 185.01 180 bottom
C4310  -  [VX_C0402_SMALL]  92.83 176.17 0 bottom
C4311  -  [VX_C0402_SMALL]  96.57 183.53 90 bottom
C4312  -  [VX_C0402_SMALL]  95.68 183.53 90 bottom
C4400  -  [VX_C0402_SMALL]  70.63 27.78 0 top
C4401  -  [VX_C0402_SMALL]  8.03 121.81 270 bottom
C4402  -  [VX_C0402_SMALL]  4.62 121.81 270 bottom
C4403  -  [VX_C0402_SMALL]  9.83 121.81 270 bottom
C4404  -  [VX_C0402_SMALL]  205.03 28.48 180 bottom
C4515  -  [VX_C0402_SMALL]  62.54 181.62 180 bottom
C4516  -  [VX_C0603_SMALL]  59.11 181.58 180 bottom
C4517  -  [VX_C0402_H24_SMALL]  50.82 184.86 270 bottom
C4518  -  [VX_C0402_H24_SMALL]  51.7 184.86 270 bottom
C4519  -  [VX_C0402_SMALL]  69.39 174.89 270 bottom
C4520  -  [VX_C0402_SMALL]  68.5 174.89 270 bottom
C4521  -  [VX_C0402_SMALL]  70.79 174.89 270 bottom
C4522  -  [VX_C0402_SMALL]  71.68 174.89 270 bottom
C4526  -  [VX_C0402_SMALL]  61.27 184.67 90 bottom
C4529  -  [VX_C0402_SMALL]  61.9 174.89 270 bottom
C4530  -  [VX_C0402_SMALL]  61.01 174.89 270 bottom
C4531  -  [VX_C0402_SMALL]  63.55 174.89 270 bottom
C4532  -  [VX_C0603_SMALL]  59.11 179.04 180 bottom
C4533  -  [VX_C0402_SMALL]  64.44 174.89 270 bottom
C4534  -  [VX_C0402_SMALL]  66.85 174.89 270 bottom
C4535  -  [VX_C0402_SMALL]  65.96 174.89 270 bottom
C4536  -  [VX_C0402_SMALL]  56.57 172.59 90 bottom
C4538  -  [VX_C0402_SMALL]  50.47 181.32 0 bottom
C4539  -  [VX_C0402_SMALL]  56.19 184.5 270 bottom
C4540  -  [VX_C0603_SMALL]  57.58 171.92 270 bottom
C4541  -  [VX_C0603_SMALL]  58.85 171.87 270 bottom
C4542  -  [VX_C0603_SMALL]  59.11 180.31 180 bottom
C4543  -  [VX_C0402_SMALL]  55.68 172.59 90 bottom
C4544  -  [VX_C0402_SMALL]  57.84 183.15 180 bottom
C4612  -  [VX_C0402_SMALL]  244.53 111.6 180 top
C4613  -  [VX_C0603_SMALL]  241.22 112.36 270 top
C4618  -  [VX_C0402_SMALL]  238.18 105.42 180 top
C4619  -  [VX_C0402_SMALL]  236.14 103.77 180 top
C4620  -  [VX_C0402_SMALL]  238.18 104.54 180 top
C4621  -  [VX_C0402_SMALL]  236.14 102.88 180 top
C4622  -  [VX_C0402_SMALL]  238.18 108.98 180 top
C4623  -  [VX_C0402_SMALL]  238.18 108.09 180 top
C4624  -  [VX_C0402_SMALL]  236.14 107.2 180 top
C4625  -  [VX_C0402_SMALL]  236.14 106.31 180 top
C4626  -  [VX_C0402_SMALL]  245.8 112.11 90 top
C4627  -  [VX_C0402_SMALL]  246.69 112.11 90 top
C4628  -  [VX_C0402_SMALL]  256.14 119.64 180 top
C4629  -  [VX_C0402_SMALL]  256.14 121.54 180 top
C4630  -  [VX_C0402_SMALL]  256.14 118.82 180 top
C4631  -  [VX_C0402_SMALL]  256.14 120.73 180 top
C4632  -  [VX_C0402_SMALL]  256.14 117.78 180 top
C4633  -  [VX_C0402_SMALL]  256.14 116.97 180 top
C4634  -  [VX_C0402_SMALL]  257.41 112.7 180 top
C4635  -  [VX_C0402_SMALL]  257.41 111.89 180 top
C4636  -  [VX_C0402_SMALL]  250.5 110.84 0 top
C4637  -  [VX_C0603_SMALL]  241.35 100.8 270 top
C4638  -  [VX_C0402_SMALL]  257.35 110.46 0 top
C4800  -  [VX_C0402_SMALL]  250.37 87.98 180 top
C4801  -  [VX_C0402_SMALL]  250.37 87.09 180 top
C4802  -  [VX_C0402_SMALL]  250.5 98.39 180 top
C4803  -  [VX_C0402_SMALL]  250.5 97.5 180 top
C4804  -  [VX_C0402_SMALL]  250.5 100.85 180 top
C4805  -  [VX_C0402_SMALL]  250.5 99.96 180 top
C4806  -  [VX_C0402_SMALL]  257.33 81.4 90 top
C4807  -  [VX_C0402_SMALL]  250.37 85.06 180 top
C4808  -  [VX_C0402_SMALL]  250.37 84.17 180 top
C4809  -  [VX_C0402_SMALL]  256.08 78.88 270 top
C4810  -  [VX_C0402_SMALL]  256.08 75.96 90 top
C5000  -  [VX_C0402_SMALL]  169.6 77.44 90 top
C5001  -  [VX_C0402_SMALL]  173.32 74.62 0 bottom
C5002  -  [VX_C0402_SMALL]  123.09 53.15 180 top
C5003  -  [VX_C0402_SMALL]  29.44 117.4 0 bottom
C5004  -  [VX_C0402_SMALL]  163.63 76.17 90 top
C5005  -  [VX_C0402_SMALL]  29.26 112.66 180 top
C5006  -  [VX_C0402_SMALL]  184.58 75.33 90 top
C5007  -  [VX_C0402_SMALL]  230.74 104.48 180 bottom
C5100  -  [VX_C0402_SMALL]  43.39 45.92 90 bottom
C5101  -  [VX_C0402_SMALL]  42.5 45.92 90 bottom
C5102  -  [VX_C0402_SMALL]  41.65 45.93 90 bottom
C5103  -  [VX_C0402_SMALL]  40.76 45.93 90 bottom
C5106  -  [VX_C0402_SMALL]  33.3 45.96 270 bottom
C5107  -  [VX_C0603_SMALL]  35.26 46.24 90 bottom
C5116  -  [VX_C0603_SMALL]  39.93 51.02 90 bottom
C5117  -  [VX_C0402_SMALL]  42.88 49.09 90 bottom
C5118  -  [VX_C0402_SMALL]  41.07 51.07 90 bottom
C5119  -  [VX_C0402_SMALL]  41.96 51.07 270 bottom
C5120  -  [VX_C0402_SMALL]  67.06 26.61 90 top
C5121  -  [VX_C0402_SMALL]  49.61 27.21 270 top
C5122  -  [VX_C0402_SMALL]  48.8 27.21 270 top
C5123  -  [VX_C0402_SMALL]  47.83 27.21 270 top
C5124  -  [VX_C0402_SMALL]  47.02 27.21 270 top
C5125  -  [VX_C0402_SMALL]  53.76 27.2 90 top
C5126  -  [VX_C0402_SMALL]  43.76 49.09 90 bottom
C5127  -  [VX_C0402_SMALL]  51.99 27.2 90 top
C5128  -  [VX_C0402_SMALL]  52.88 27.2 90 top
C5131  -  [VX_C0402_SMALL]  58.47 27.2 270 top
C5132  -  [VX_C0402_SMALL]  57.66 27.2 270 top
C5133  -  [VX_C0402_SMALL]  62.86 26.6 90 top
C5134  -  [VX_C0402_SMALL]  65.38 26.6 90 top
C5135  -  [VX_C0402_SMALL]  63.7 26.6 90 top
C5136  -  [VX_C0402_SMALL]  64.54 26.6 90 top
C5137  -  [VX_C0402_SMALL]  66.22 26.6 90 top
C5138  -  [VX_C0402_SMALL]  42.85 51.07 270 bottom
C5139  -  [VX_C0402_SMALL]  43.74 51.07 270 bottom
C5140  -  [VX_C0402_SMALL]  26.34 39.26 0 top
C5141  -  [VX_C0402_SMALL]  26.34 38.24 0 top
C5142  -  [VX_C0402_SMALL]  26.34 37.23 0 top
C5143  -  [VX_C0402_SMALL]  26.34 36.21 0 top
C5144  -  [VX_C0402_SMALL]  25.32 23.51 270 top
C5145  -  [VX_C0805_H57_SMALL]  26.59 23.97 90 top
C5147  -  [VX_C0402_SMALL]  34.19 45.96 270 bottom
C5150  -  [VX_C0402_SMALL]  60.19 27.2 270 top
C5151  -  [VX_C0402_SMALL]  59.37 27.2 270 top
C5154  -  [VX_C0402_SMALL]  61.12 27.2 270 top
C5155  -  [VX_C0402_SMALL]  61.93 27.2 270 top
C5158  -  [VX_C0402_SMALL]  42.09 27.21 270 top
C5159  -  [VX_C0402_SMALL]  42.98 27.21 270 top
C5160  -  [VX_C0603_H39_SMALL]  36.53 46.24 90 bottom
C5161  -  [VX_C0603_H39_SMALL]  68.1 26.92 270 top
C5162  -  [VX_C0603_H39_SMALL]  50.88 27.04 270 top
C5167  -  [VX_C0402_SMALL]  32.41 45.96 270 bottom
C5168  -  [VX_C0402_SMALL]  41.99 49.09 90 bottom
C5169  -  [VX_C0805_H57_SMALL]  26.47 26.94 270 top
C5171  -  [VX_C0402_SMALL]  25.45 35.32 0 top
C5172  -  [VX_C0402_SMALL]  154.99 20.16 90 top
C5173  -  [VX_C0402_SMALL]  159.31 29.43 0 top
C5174  -  [VX_C0402_SMALL]  26.72 45.05 270 top
C5175  -  [VX_C0603_SMALL]  162.1 22.83 270 top
C5200  -  [VX_C0402_SMALL]  254.05 59.4 0 top
C5201  -  [VX_C0402_SMALL]  253.8 56.91 270 top
C5202  -  [VX_C0402_SMALL]  254.69 56.91 270 top
C5300  -  [VX_C0603_SMALL]  238.56 92.09 270 top
C5301  -  [VX_C0402_SMALL]  240.84 88.03 90 top
C5302  -  [VX_C0402_SMALL]  242.37 84.42 90 top
C5303  -  [VX_C0402_SMALL]  237.41 91.96 90 top
C5306  -  [VX_C0402_SMALL]  251.51 89.93 270 top
C5307  -  [VX_C0402_SMALL]  252.78 89.93 90 top
C5501  -  [VX_C0402_SMALL]  256.11 67.79 270 top
C5502  -  [VX_C0603_SMALL]  256.29 36.42 270 top
C5503  -  [VX_C0402_SMALL]  257.35 37.3 90 top
C5505  -  [VX_C0603_H39_SMALL]  255.07 67.91 90 top
C5506  -  [VX_C0603_H39_SMALL]  255.02 36.42 270 top
C5507  -  [VX_C0402_SMALL]  244.65 60.16 0 top
C5600  -  [VX_C0402_SMALL]  40.56 184.12 0 top
C5801  -  [VX_C0402_SMALL]  251.89 130.57 180 top
C5802  -  [VX_C0402_SMALL]  252.15 122.82 270 top
C5803  -  [VX_C0603_SMALL]  251.89 131.71 0 top
C6001  -  [VX_C0402_SMALL]  249.45 70.45 0 bottom
C6002  -  [VX_C0402_SMALL]  14.02 99.03 180 top
C6003  -  [VX_C0402_SMALL]  22.09 109.09 0 top
C6200  -  [VX_C0402_SMALL]  186.66 30.14 180 top
C6201  -  [VX_C0603_SMALL]  185.22 30.6 90 top
C6202  -  [VX_C0402_SMALL]  181.86 30.34 270 top
C6203  -  [VX_C0402_SMALL]  184.96 20.33 0 top
C6204  -  [VX_C0402_SMALL]  181.66 20.33 0 top
C6205  -  [VX_C0402_SMALL]  186.61 20.33 180 top
C6206  -  [VX_C0805_H57_SMALL]  180.57 30.83 270 top
C6700  -  [VX_C0402_SMALL]  10.72 103.85 90 top
C6704  -  [VX_C0402_SMALL]  12.62 69.74 270 top
C6705  -  [VX_C0402_SMALL]  10.85 70.5 0 top
C6707  -  [VX_C0402_SMALL]  5.64 107.79 90 top
C7000  -  [VX_C0402_SMALL]  98.98 147.59 180 top
C7001  -  [VX_C0603_SMALL]  92.4 166.09 90 bottom
C7002  -  [VX_C0805_H57_SMALL]  89.33 162.83 0 top
C7003  -  [VX_C0603_H39_SMALL]  96.7 144.69 180 top
C7004  -  [VX_C0402_SMALL]  75.74 126.51 0 bottom
C7005  -  [VX_C0402_SMALL]  72.82 127.9 0 bottom
C7006  -  [VX_C0603_SMALL]  89.59 164.3 180 bottom
C7007  -  [VX_C0805_H57_SMALL]  89.33 166.46 0 top
C7008  -  [VX_C0603_H39_SMALL]  93.67 166.11 90 bottom
C7009  -  [VX_C0402_SMALL]  75.74 129.05 0 bottom
C7010  -  [VX_C0402_SMALL]  75.74 129.94 0 bottom
C7011  -  [VX_C0402_SMALL]  98.98 146.7 180 top
C7012  -  [VX_C0805_H57_SMALL]  93.9 164.23 180 top
C7013  -  [VX_C0603_H39_SMALL]  93.65 162.7 0 top
C7014  -  [VX_C0402_SMALL]  75.74 127.4 0 bottom
C7015  -  [VX_C0402_SMALL]  72.82 128.79 0 bottom
C7016  -  [VX_C0402_SMALL]  99.87 144.03 180 top
C7017  -  [VX_C0402_SMALL]  99.87 143.14 180 top
C7018  -  [VX_C0805_H57_SMALL]  89.33 164.61 0 top
C7019  -  [VX_C0603_H39_SMALL]  91.11 166.08 90 bottom
C7020  -  [VX_C0402_SMALL]  72.82 131.33 0 bottom
C7021  -  [VX_C0402_SMALL]  72.82 130.44 0 bottom
C7022  -  [VX_C0402_SMALL]  75.74 131.59 0 bottom
C7023  -  [VX_C0402_SMALL]  75.74 132.48 0 bottom
C7024  -  [VX_C0402_SMALL]  72.82 133.87 0 bottom
C7025  -  [VX_C0402_SMALL]  72.82 132.98 0 bottom
C7026  -  [VX_C0402_SMALL]  98.98 145.81 180 top
C7027  -  [VX_C0603_SMALL]  91.87 133.36 270 top
C7028  -  [VX_C0603_SMALL]  93.14 133.36 270 top
C7029  -  [VX_C0402_SMALL]  75.74 134.13 0 bottom
C7030  -  [VX_C0402_SMALL]  75.74 135.02 0 bottom
C7031  -  [VX_C0402_SMALL]  72.82 136.41 0 bottom
C7032  -  [VX_C0402_SMALL]  72.82 135.52 0 bottom
C7033  -  [VX_C0402_SMALL]  75.74 136.67 0 bottom
C7034  -  [VX_C0402_SMALL]  75.74 137.58 0 bottom
C7035  -  [VX_C0402_SMALL]  72.82 137.94 0 bottom
C7036  -  [VX_C0402_SMALL]  72.82 138.83 0 bottom
C7037  -  [VX_C0402_SMALL]  75.74 140.1 0 bottom
C7038  -  [VX_C0402_SMALL]  75.74 139.21 0 bottom
C7039  -  [VX_C0402_SMALL]  72.82 140.6 0 bottom
C7040  -  [VX_C0402_SMALL]  72.82 141.49 0 bottom
C7041  -  [VX_C0402_SMALL]  75.74 141.95 0 bottom
C7042  -  [VX_C0402_SMALL]  75.74 142.84 0 bottom
C7043  -  [VX_C0402_SMALL]  72.82 143.14 0 bottom
C7044  -  [VX_C0402_SMALL]  72.82 144.03 0 bottom
C7045  -  [VX_C0402_SMALL]  99.87 142.25 180 top
C7046  -  [VX_C0402_SMALL]  99.87 141.37 180 top
C7047  -  [VX_C0603_SMALL]  99.56 140.32 0 top
C7048  -  [VX_C0402_SMALL]  99.89 144.92 180 top
C7049  -  [VX_C0402_SMALL]  75.74 144.54 0 bottom
C7050  -  [VX_C0402_SMALL]  75.74 145.43 0 bottom
C7051  -  [VX_C0402_SMALL]  73.46 145.81 0 bottom
C7052  -  [VX_C0402_SMALL]  73.46 146.7 0 bottom
C7100  -  [VX_C0402_SMALL]  105.75 152.85 0 top
C7101  -  [VX_C0402_SMALL]  120.9 149.62 180 top
C7102  -  [VX_C0603_H39_SMALL]  102.79 165.24 90 bottom
C7103  -  [VX_C0402_SMALL]  110.72 152.41 270 top
C7104  -  [VX_C0402_SMALL]  113.08 152.41 270 top
C7105  -  [VX_C0402_SMALL]  113.08 129.3 90 top
C7106  -  [VX_C0402_SMALL]  119.18 142.69 0 top
C7107  -  [VX_C0402_SMALL]  120.9 150.89 180 top
C7200  -  [VX_C0603_SMALL]  99.87 136.03 270 top
C7206  -  [VX_C0603_SMALL]  79.93 154.19 180 top
C7207  -  [VX_C0603_SMALL]  79.93 152.92 180 top
C7208  -  [VX_C0402_SMALL]  80.57 151.53 90 top
C7209  -  [VX_C0805_H57_SMALL]  82.98 154.19 180 top
C7210  -  [VX_C0402_SMALL]  78.79 151.53 270 top
C7211  -  [VX_C0805_H57_SMALL]  96.7 164.99 90 top
C7212  -  [VX_C0402_SMALL]  110.54 129.3 90 top
C7213  -  [VX_C0402_SMALL]  100.7 126.33 0 top
C7214  -  [VX_C0402_SMALL]  119.18 137.81 0 top
C7215  -  [VX_C0402_SMALL]  95.56 118 0 bottom
C7216  -  [VX_C0402_SMALL]  97.21 118 180 bottom
C7219  -  [VX_C0603_SMALL]  90.48 130.44 90 top
C7220  -  [VX_C0201_H14]  96.65 131.08 90 top
C7221  -  [VX_C0402_SMALL]  92.51 130.82 270 top
C7222  -  [VX_C0402_SMALL]  95.16 128.08 90 top
C7223  -  [VX_C0603_SMALL]  92.89 128.87 90 top
C7224  -  [VX_C0201_H14]  96.31 129.69 180 top
C7225  -  [VX_C0402_SMALL]  96.94 128.08 90 top
C7226  -  [VX_C0402_SMALL]  96.05 128.08 90 top
C7227  -  [VX_C0402_SMALL]  91.62 130.82 270 top
C7228  -  [VX_C0402_SMALL]  99.62 137.56 180 top
C7229  -  [VX_C0402_SMALL]  97.97 137.43 0 top
C7301  -  [VX_C0402_SMALL]  98.1 132.07 0 top
C7302  -  [VX_C0402_SMALL]  98.53 126.33 180 top
C7303  -  [VX_C0402_SMALL]  99.87 131.59 180 top
C7304  -  [VX_C0402_SMALL]  98.53 127.22 180 top
C7306  -  [VX_C0402_SMALL]  98.27 130.04 0 top
C7307  -  [VX_C0402_SMALL]  99.87 130.7 180 top
C7308  -  [VX_C0402_SMALL]  98.27 130.88 0 top
C7400  -  [VX_C0402_SMALL]  86.54 126.89 0 top
C7401  -  [VX_C0402_SMALL]  104.37 112.71 180 bottom
C7500  -  [VX_C0402_SMALL]  119.15 139.09 0 top
C7501  -  [VX_C0402_SMALL]  107.49 152.41 270 top
C7502  -  [VX_C0402_SMALL]  119.18 136.92 0 top
C7503  -  [VX_C0402_SMALL]  120.83 136.92 180 top
C7504  -  [VX_C0402_SMALL]  124.95 158.15 90 top
C7505  -  [VX_C0402_SMALL]  114.35 152.54 270 top
C7506  -  [VX_C0402_SMALL]  109.88 152.41 270 top
C7507  -  [VX_C0402_SMALL]  120.14 152.16 90 top
C7508  -  [VX_C0805_H57_SMALL]  106.99 137.3 180 top
C7509  -  [VX_C0805_H57_SMALL]  86.59 152.67 0 top
C7510  -  [VX_C0805_H57_SMALL]  86.59 154.45 0 top
C7511  -  [VX_C0805_H57_SMALL]  106.99 144.39 180 top
C7512  -  [VX_C0805_H57_SMALL]  106.99 139.08 180 top
C7513  -  [VX_C0805_H57_SMALL]  106.99 142.61 180 top
C7514  -  [VX_C0805_H57_SMALL]  102.18 145.58 0 top
C7515  -  [VX_C0805_H57_SMALL]  92.8 161.21 180 top
C7516  -  [VX_C0805_H57_SMALL]  96.19 160.88 270 top
C7517  -  [VX_C0805_H57_SMALL]  92.66 151.94 90 top
C7518  -  [VX_C0805_H57_SMALL]  106.99 135.52 180 top
C7519  -  [VX_C0603_SMALL]  116.78 138.81 180 top
C7520  -  [VX_C0603_SMALL]  116.79 133.75 180 top
C7521  -  [VX_C0603_SMALL]  116.78 136.27 180 top
C7522  -  [VX_C0603_SMALL]  116.78 137.54 180 top
C7523  -  [VX_C0805_H57_SMALL]  106.99 140.86 180 top
C7524  -  [VX_C0402_SMALL]  119.18 146.32 0 top
C7525  -  [VX_C0402_SMALL]  119.17 144.49 0 top
C7526  -  [VX_C0402_SMALL]  117.69 129.73 90 top
C7527  -  [VX_C0402_SMALL]  119.19 145.39 0 top
C7528  -  [VX_C0402_SMALL]  119.15 140.23 0 top
C7529  -  [VX_C0402_SMALL]  125.04 156.91 0 top
C7530  -  [VX_C0402_SMALL]  119.18 135.5 0 top
C7531  -  [VX_C0402_SMALL]  119.18 141.42 0 top
C7532  -  [VX_C0402_SMALL]  120.98 152.16 90 top
C7533  -  [VX_C0402_SMALL]  109.71 130.32 90 top
C7534  -  [VX_C0402_SMALL]  119.18 143.52 0 top
C7535  -  [VX_C0402_SMALL]  115.78 129.76 90 top
C7536  -  [VX_C0402_SMALL]  114.12 130.32 90 top
C7537  -  [VX_C0402_SMALL]  111.56 152.41 270 top
C7538  -  [VX_C0603_SMALL]  110.19 141.37 180 top
C7539  -  [VX_C0603_SMALL]  113.81 141.38 0 top
C7540  -  [VX_C0603_SMALL]  116.78 140.08 180 top
C7541  -  [VX_C0603_SMALL]  98.22 160.67 90 top
C7542  -  [VX_C0603_SMALL]  113.81 142.65 0 top
C7543  -  [VX_C0603_SMALL]  113.81 136.3 0 top
C7544  -  [VX_C0603_SMALL]  102.18 141.49 180 top
C7545  -  [VX_C0603_SMALL]  110.19 135.02 180 top
C7546  -  [VX_C0603_SMALL]  113.81 135.03 0 top
C7547  -  [VX_C0603_SMALL]  116.78 135 180 top
C7548  -  [VX_C0603_SMALL]  117.15 131.84 0 top
C7549  -  [VX_C0603_SMALL]  114.91 131.84 180 top
C7550  -  [VX_C0603_SMALL]  119.37 133.86 180 top
C7551  -  [VX_C0603_SMALL]  119.1 152.16 270 top
C7552  -  [VX_C0603_SMALL]  126.9 168.43 180 top
C7553  -  [VX_C0603_SMALL]  118.99 147.83 180 top
C7554  -  [VX_C0603_SMALL]  115.39 152.06 90 top
C7555  -  [VX_C0603_SMALL]  112.19 131.84 0 top
C7556  -  [VX_C0603_SMALL]  109.93 131.84 180 top
C7557  -  [VX_C0603_SMALL]  119.43 131.84 180 top
C7558  -  [VX_C0603_SMALL]  99.48 161.58 90 top
C7559  -  [VX_C0603_SMALL]  116.78 141.35 180 top
C7560  -  [VX_C0603_SMALL]  100.28 155.92 90 top
C7561  -  [VX_C0603_SMALL]  110.19 143.91 180 top
C7562  -  [VX_C0603_SMALL]  113.81 143.92 0 top
C7563  -  [VX_C0603_SMALL]  110.19 145.18 180 top
C7564  -  [VX_C0603_SMALL]  110.19 138.83 180 top
C7565  -  [VX_C0603_SMALL]  113.81 138.84 0 top
C7566  -  [VX_C0603_SMALL]  102.18 140.22 180 top
C7567  -  [VX_C0603_SMALL]  116.78 145.16 180 top
C7568  -  [VX_C0603_SMALL]  121.2 155.17 90 top
C7569  -  [VX_C0603_SMALL]  122.47 155.17 90 top
C7570  -  [VX_C0603_SMALL]  104.82 167.25 270 top
C7571  -  [VX_C0603_SMALL]  123.74 155.17 90 top
C7572  -  [VX_C0603_SMALL]  103.89 152.11 90 top
C7573  -  [VX_C0603_SMALL]  117.88 152.16 270 top
C7574  -  [VX_C0805_H57_SMALL]  109.07 117.36 0 top
C7575  -  [VX_C0805_H57_SMALL]  109.07 115.58 0 top
C7576  -  [VX_C0805_H57_SMALL]  130.26 161.07 270 top
C7577  -  [VX_C0805_H57_SMALL]  109.14 113.81 0 top
C7578  -  [VX_C0805_H57_SMALL]  128.48 161.07 270 top
C7579  -  [VX_C0805_H57_SMALL]  132.04 161.07 270 top
C7580  -  [VX_C0603_SMALL]  102.18 144.03 180 top
C7581  -  [VX_C0603_SMALL]  102.18 138.95 180 top
C7582  -  [VX_C0603_SMALL]  102.18 135.14 180 top
C7583  -  [VX_C0603_SMALL]  107.12 145.85 0 top
C7584  -  [VX_C0603_SMALL]  113.81 140.11 0 top
C7585  -  [VX_C0603_SMALL]  116.78 143.89 180 top
C7586  -  [VX_C0603_SMALL]  110.19 137.56 180 top
C7587  -  [VX_C0603_SMALL]  113.81 137.57 0 top
C7588  -  [VX_C0603_SMALL]  116.78 142.62 180 top
C7589  -  [VX_C0603_SMALL]  102.29 152.16 90 top
C7590  -  [VX_C0402_SMALL]  99.87 132.48 180 top
C7591  -  [VX_C0402_SMALL]  96.44 134.89 270 top
C7592  -  [VX_C0402_SMALL]  97.33 134.89 270 top
C7593  -  [VX_C0603_SMALL]  90.73 133.36 270 top
C7594  -  [VX_C0402_SMALL]  99.87 134.46 180 top
C7595  -  [VX_C0402_SMALL]  99.87 133.37 180 top
C7596  -  [VX_C0603_SMALL]  96.44 133.09 180 top
C7597  -  [VX_C0603_SMALL]  102.18 137.68 180 top
C7598  -  [VX_C0603_SMALL]  102.18 136.41 180 top
C7599  -  [VX_C0603_SMALL]  110.19 133.75 180 top
C7600  -  [VX_C0402_SMALL]  124.03 181.22 180 top
C7603  -  [VX_C0402_SMALL]  117.53 176.37 90 top
C7604  -  [VX_C0402_SMALL]  110.76 183.07 0 top
C7605  -  [VX_C0402_SMALL]  116.64 176.37 270 top
C7606  -  [VX_C0402_SMALL]  125.78 184.67 0 bottom
C7607  -  [VX_C0402_SMALL]  127.56 168.29 90 bottom
C7608  -  [VX_C0402_SMALL]  128.96 168.29 90 bottom
C7609  -  [VX_C0402_SMALL]  110.76 181.31 0 top
C7610  -  [VX_C0402_SMALL]  118.05 182.91 0 top
C7611  -  [VX_C0402_SMALL]  118.42 184.67 180 bottom
C7612  -  [VX_C0402_SMALL]  123.5 179.47 90 top
C7613  -  [VX_C0402_SMALL]  104.06 173.54 90 top
C7614  -  [VX_C0402_SMALL]  117.45 168.44 180 bottom
C7615  -  [VX_C0402_SMALL]  127.51 174.5 0 top
C7616  -  [VX_C0402_SMALL]  118.05 181.89 0 top
C7617  -  [VX_C0402_SMALL]  115.84 172.63 90 top
C7618  -  [VX_C0402_SMALL]  130.61 173.27 270 top
C7619  -  [VX_C0402_SMALL]  128.07 170 180 top
C7620  -  [VX_C0603_SMALL]  122.1 184.8 0 bottom
C7621  -  [VX_C0603_SMALL]  129.46 184.8 0 bottom
C7622  -  [VX_C0402_SMALL]  103.43 183.28 270 bottom
C7623  -  [VX_C0402_SMALL]  115.21 179.7 270 top
C7624  -  [VX_C0402_SMALL]  110.76 179.84 0 top
C7625  -  [VX_C0402_SMALL]  113.72 167.78 180 bottom
C7626  -  [VX_C0402_SMALL]  113.72 168.67 180 bottom
C7627  -  [VX_C0402_SMALL]  115.88 184.67 180 bottom
C7628  -  [VX_C0402_SMALL]  103.35 180.28 90 bottom
C7629  -  [VX_C0402_SMALL]  104.83 168.29 90 bottom
C7630  -  [VX_C0402_SMALL]  105.72 168.29 90 bottom
C7631  -  [VX_C0402_SMALL]  105.97 176.44 0 top
C7632  -  [VX_C0402_SMALL]  125.5 180.25 180 top
C7633  -  [VX_C0402_SMALL]  130.86 170.91 90 top
C7634  -  [VX_C0402_SMALL]  117.27 180.99 180 top
C7635  -  [VX_C0402_SMALL]  108.51 184.67 180 bottom
C7636  -  [VX_C0603_SMALL]  112.7 184.8 180 bottom
C7637  -  [VX_C0603_SMALL]  105.08 184.8 180 bottom
C7700  -  [VX_C0402_SMALL]  155.75 163.59 180 bottom
C7703  -  [VX_C0402_SMALL]  148.88 167.26 180 top
C7704  -  [VX_C0402_SMALL]  157.15 173.5 180 bottom
C7705  -  [VX_C0402_SMALL]  147.28 169.04 0 top
C7706  -  [VX_C0402_SMALL]  157.15 177.18 180 bottom
C7707  -  [VX_C0402_SMALL]  150.27 180.84 0 top
C7708  -  [VX_C0402_SMALL]  151.94 174.64 0 top
C7709  -  [VX_C0402_SMALL]  146.1 182.77 270 bottom
C7710  -  [VX_C0402_SMALL]  154.99 176.29 0 top
C7711  -  [VX_C0402_SMALL]  145.54 168.98 180 top
C7712  -  [VX_C0402_SMALL]  151.94 169.16 0 top
C7713  -  [VX_C0402_SMALL]  154.99 174.64 180 top
C7714  -  [VX_C0402_SMALL]  140.77 170.19 270 bottom
C7715  -  [VX_C0402_SMALL]  154.74 169.18 180 top
C7716  -  [VX_C0402_SMALL]  140.67 178.32 270 bottom
C7717  -  [VX_C0402_SMALL]  150.29 182.77 0 bottom
C7718  -  [VX_C0402_SMALL]  157.15 171.34 180 bottom
C7719  -  [VX_C0402_SMALL]  152.45 182.77 180 bottom
C7720  -  [VX_C0603_SMALL]  142.42 183.02 90 bottom
C7721  -  [VX_C0603_SMALL]  155.5 183.15 90 bottom
C7722  -  [VX_C0402_SMALL]  155.78 157.19 180 bottom
C7723  -  [VX_C0402_SMALL]  155.78 159.6 180 bottom
C7724  -  [VX_C0402_SMALL]  149.81 162.57 0 top
C7725  -  [VX_C0402_SMALL]  151.94 168.27 0 top
C7726  -  [VX_C0402_SMALL]  150.42 155.49 180 top
C7727  -  [VX_C0402_SMALL]  152.9 158 180 top
C7728  -  [VX_C0402_SMALL]  153.59 155.46 0 top
C7729  -  [VX_C0402_SMALL]  138.94 166.97 270 bottom
C7730  -  [VX_C0402_SMALL]  152.48 162.7 180 top
C7731  -  [VX_C0402_SMALL]  154.74 168.29 180 top
C7732  -  [VX_C0402_SMALL]  155.78 156.17 180 bottom
C7733  -  [VX_C0402_SMALL]  150.01 161.15 0 top
C7734  -  [VX_C0402_SMALL]  152.58 161.18 180 top
C7735  -  [VX_C0402_SMALL]  138.94 165.27 90 bottom
C7736  -  [VX_C0603_SMALL]  155.91 154.78 0 bottom
C7737  -  [VX_C0603_SMALL]  156.03 158.46 0 bottom
C7800  -  [VX_C0402_SMALL]  155.61 124.55 180 bottom
C7803  -  [VX_C0402_SMALL]  147.5 129.94 270 bottom
C7804  -  [VX_C0402_SMALL]  142.47 147.28 180 top
C7805  -  [VX_C0402_SMALL]  146.62 141.33 0 bottom
C7806  -  [VX_C0402_SMALL]  141.64 153.86 180 top
C7807  -  [VX_C0402_SMALL]  141.94 141.3 0 bottom
C7808  -  [VX_C0402_SMALL]  155.63 144.41 180 bottom
C7809  -  [VX_C0402_SMALL]  153.59 154.57 0 top
C7810  -  [VX_C0402_SMALL]  139.67 152.44 270 top
C7811  -  [VX_C0402_SMALL]  149.91 149.11 0 top
C7812  -  [VX_C0402_SMALL]  152.96 149.24 180 top
C7813  -  [VX_C0402_SMALL]  150.42 154.6 0 top
C7814  -  [VX_C0402_SMALL]  155.6 147.77 180 bottom
C7815  -  [VX_C0402_SMALL]  155.63 153.68 180 bottom
C7816  -  [VX_C0402_SMALL]  152.96 147.46 180 top
C7817  -  [VX_C0402_SMALL]  148.77 140.98 90 bottom
C7818  -  [VX_C0402_SMALL]  149.78 147.59 0 top
C7819  -  [VX_C0402_SMALL]  151.44 140.98 90 bottom
C7820  -  [VX_C0603_SMALL]  155.96 143.32 0 bottom
C7821  -  [VX_C0603_SMALL]  155.88 151.78 0 bottom
C7822  -  [VX_C0402_SMALL]  155.63 119.14 180 bottom
C7823  -  [VX_C0402_SMALL]  152.58 116.04 0 top
C7824  -  [VX_C0402_SMALL]  149.28 116.04 0 top
C7825  -  [VX_C0402_SMALL]  152.83 121.93 180 top
C7826  -  [VX_C0402_SMALL]  143.31 117.06 0 top
C7827  -  [VX_C0402_SMALL]  150.93 116.04 0 top
C7828  -  [VX_C0402_SMALL]  141.28 129.63 0 bottom
